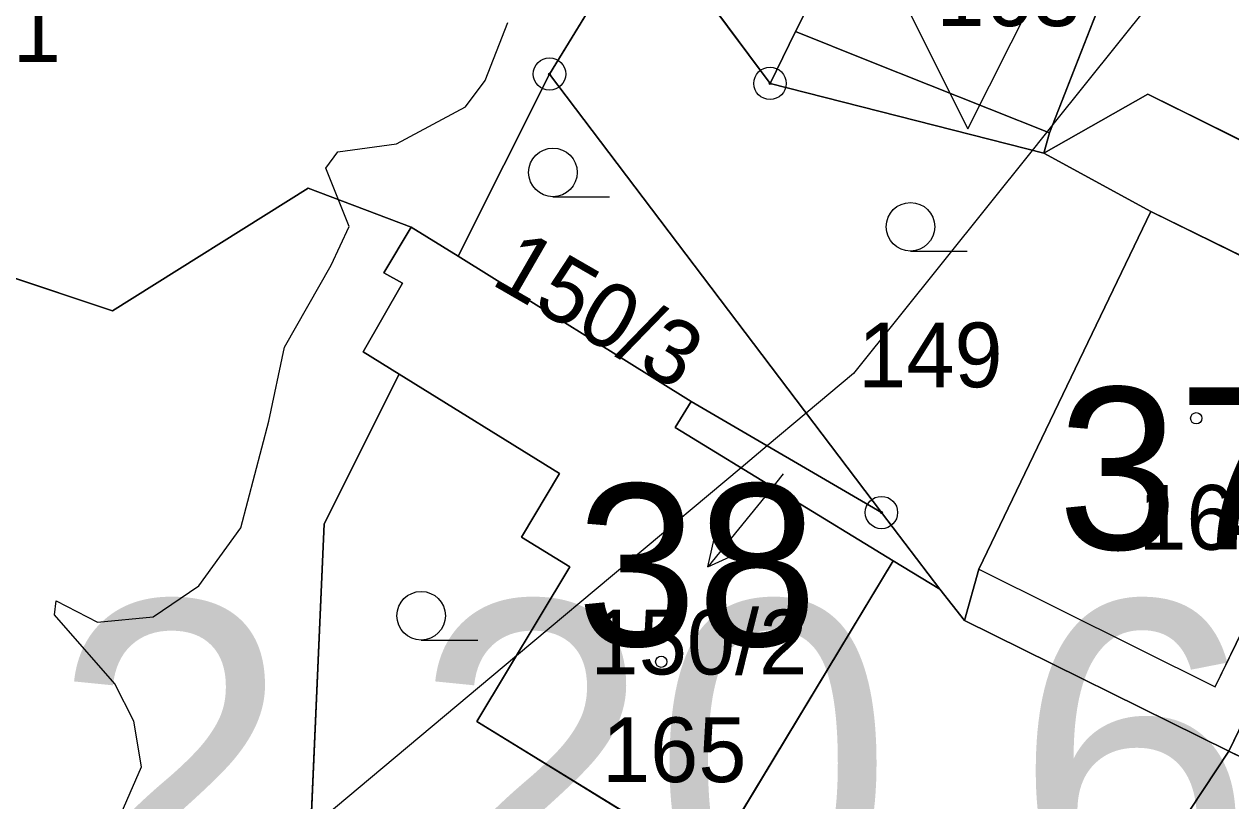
# Model space of a CAD drawing. Extents: x -706130 to -698555, y -971544 to -967260.
# Drawn here: x -704406.86 to -704369.6, y -970257.43 to -970233.43 of the extents above; entities that cross this region are included whole.
import ezdxf

# ---------------------------------------------------------------- set-up
doc = ezdxf.new("R2010")
doc.units = 0
for name, color, linetype in [('Architektonicky cenná stavba S', 7, 'Continuous'), ('BPEJ hranice S', 7, 'Continuous'), ('BPEJ I-II trida ochrany S', 7, 'Continuous'), ('Docházková izochrona - BUS S', 7, 'Continuous'), ('Docházková izochrona - VLAK N', 7, 'Continuous'), ('KN_Budovy', 7, 'Continuous'), ('KN_Budovy_cisla_domovni', 7, 'Continuous'), ('KN_Hranice_parcel', 7, 'Continuous'), ('KN_Hranice_parcel_vnitrni_kresba', 7, 'Continuous'), ('KN_Parcelni cisla', 7, 'Continuous'), ('KN_Parcelni cisla_sipky', 7, 'Continuous'), ('KN_Polygon parcely', 7, 'Continuous'), ('KN_POZEMKY_13_ZASTAVENA PLOCHA', 7, 'Continuous'), ('KN_POZEMKY_14_OSTATNI PLOCHA', 7, 'Continuous'), ('KN_POZEMKY_5_ZAHRADA', 7, 'Continuous'), ('KN_VYUZITI_17_ostatni plocha_ostatni komunikace', 7, 'Continuous'), ('KN_VYUZITI_23_ostatni plocha_manipulacni plocha', 7, 'Continuous'), ('KN_Značky bodu BP', 7, 'Continuous'), ('KN_Značky budov', 7, 'Continuous'), ('KN_Značky kultur', 7, 'Continuous'), ('Regulační kódy zastavěné S', 7, 'Continuous'), ('Záplavové území stanovene S', 7, 'Continuous')]:
    doc.layers.add(name, color=color, linetype=linetype)

msp = doc.modelspace()

# ---------------------------------------------------------------- linework, layer by layer
at = {"layer": 'Architektonicky cenná stavba S'}
msp.add_lwpolyline([(-704377.717, -970224.668), (-704379.717, -970228.668), (-704383.717, -970230.668), (-704379.717, -970232.668), (-704377.717, -970236.668), (-704375.717, -970232.668), (-704371.717, -970230.668), (-704375.717, -970228.668)], close=True, dxfattribs=at)
at = {"layer": 'BPEJ hranice S'}
msp.add_lwpolyline([(-704367.782, -970225.844), (-704370.102, -970230.283), (-704375.1, -970236.533), (-704375.737, -970237.329), (-704381.252, -970244.227), (-704382.712, -970245.45), (-704383.916, -970246.459), (-704384.724, -970247.136), (-704391.663, -970252.952), (-704398.01, -970258.272), (-704400.038, -970259.971), (-704404.172, -970263.437), (-704405.573, -970264.137), (-704409.891, -970266.297), (-704417.181, -970269.944), (-704427.092, -970270.254), (-704432.635, -970270.254), (-704437.933, -970270.254), (-704450.012, -970264.987)], dxfattribs=at)
at = {"layer": 'BPEJ I-II trida ochrany S'}
for p, q in [((-704375.38, -970237.42), (-704375.737, -970237.329)), ((-704372.07, -970239.22), (-704375.38, -970237.42)), ((-704377.38, -970250.27), (-704372.07, -970239.22)), ((-704382.712, -970245.45), (-704383.916, -970246.459)), ((-704383.916, -970246.459), (-704383.916, -970246.459)), ((-704384.724, -970247.136), (-704380.03, -970250.01)), ((-704380.03, -970250.01), (-704378.59, -970250.89)), ((-704377.82, -970251.86), (-704377.38, -970250.27)), ((-704378.59, -970250.89), (-704377.82, -970251.86)), ((-704392.88, -970254.98), (-704391.662, -970252.951)), ((-704385.69, -970259.4), (-704392.88, -970254.98))]:
    msp.add_line(p, q, dxfattribs=at)
for points in [[(-704375.737, -970237.329), (-704375.737, -970237.329), (-704381.252, -970244.227), (-704382.712, -970245.45), (-704382.712, -970245.45)], [(-704383.916, -970246.459), (-704384.724, -970247.136), (-704384.724, -970247.136)], [(-704391.662, -970252.951), (-704391.663, -970252.952), (-704398.01, -970258.272)]]:
    msp.add_lwpolyline(points, dxfattribs=at)
at = {"layer": 'Docházková izochrona - BUS S'}
msp.add_arc((-704361.829, -969946.93), 400, 155.51821, 17.33949, dxfattribs=at)
at = {"layer": 'Docházková izochrona - VLAK N'}
msp.add_circle((-704165.451, -969778.767), 800, dxfattribs=at)
at = {"layer": 'KN_Budovy'}
for points in [[(-704385.39, -970230.55), (-704382.18, -970231.93), (-704383.04, -970233.66), (-704380.79, -970234.56), (-704375.2, -970236.79), (-704371.02, -970226.09), (-704376.75, -970223.62), (-704378.47, -970227.61), (-704380.88, -970226.58), (-704380.37, -970225.41), (-704381.49, -970224.93), (-704382.03, -970226.17), (-704383.27, -970225.63)], [(-704372.07, -970239.22), (-704377.38, -970250.27), (-704370.08, -970253.91), (-704365.36, -970244.15), (-704368.12, -970242.72), (-704367.55, -970241.44)], [(-704395.18, -970241.43), (-704396.39, -970243.55), (-704395.28, -970244.24), (-704390.33, -970247.31), (-704391.5, -970249.28), (-704390.01, -970250.2), (-704392.88, -970254.98), (-704385.69, -970259.4), (-704380.03, -970250.01), (-704386.76, -970245.89), (-704386.26, -970245.09), (-704393.46, -970240.6), (-704394.91, -970239.7), (-704395.76, -970241.11)]]:
    msp.add_lwpolyline(points, close=True, dxfattribs=at)
at = {"layer": 'KN_Hranice_parcel'}
for p, q in [((-704388.54, -970231.53), (-704390.64, -970234.97)), ((-704404.13, -970242.29), (-704430.43, -970233.49)), ((-704393.46, -970240.6), (-704390.64, -970234.97)), ((-704390.64, -970234.97), (-704380.39, -970248.52)), ((-704383.83, -970235.26), (-704375.38, -970237.42)), ((-704372.07, -970239.22), (-704375.38, -970237.42)), ((-704393.46, -970240.6), (-704394.91, -970239.7)), ((-704386.26, -970245.09), (-704393.46, -970240.6)), ((-704396.39, -970243.55), (-704395.28, -970244.24)), ((-704395.28, -970244.24), (-704390.33, -970247.31)), ((-704380.39, -970248.52), (-704386.26, -970245.09)), ((-704390.33, -970247.31), (-704391.5, -970249.28)), ((-704380.39, -970248.52), (-704378.59, -970250.89)), ((-704385.69, -970259.4), (-704380.03, -970250.01)), ((-704378.59, -970250.89), (-704380.03, -970250.01)), ((-704378.59, -970250.89), (-704377.82, -970251.86)), ((-704377.82, -970251.86), (-704369.66, -970255.89)), ((-704374.96, -970263.92), (-704369.66, -970255.89))]:
    msp.add_line(p, q, dxfattribs=at)
for points in [[(-704371.02, -970226.09), (-704376.75, -970223.62), (-704378.47, -970227.61), (-704380.88, -970226.58), (-704380.37, -970225.41), (-704381.49, -970224.93), (-704382.03, -970226.17), (-704383.27, -970225.63), (-704385.39, -970230.55), (-704382.18, -970231.93), (-704383.04, -970233.66), (-704383.83, -970235.26)], [(-704375.38, -970237.42), (-704375.2, -970236.79), (-704371.02, -970226.09)], [(-704387.66, -970230.08), (-704385.82, -970232.57), (-704383.83, -970235.26)], [(-704375.38, -970237.42), (-704372.16, -970235.59), (-704358.88, -970242.2), (-704356.76, -970243.29)], [(-704394.91, -970239.7), (-704398.09, -970238.5), (-704404.13, -970242.29)], [(-704372.07, -970239.22), (-704377.38, -970250.27), (-704377.82, -970251.86)], [(-704369.66, -970255.89), (-704363.61, -970243.38), (-704367.55, -970241.44), (-704372.07, -970239.22)], [(-704394.91, -970239.7), (-704395.76, -970241.11), (-704395.18, -970241.43), (-704396.39, -970243.55)], [(-704398.11, -970260.57), (-704397.6, -970248.87), (-704395.28, -970244.24)], [(-704380.03, -970250.01), (-704386.76, -970245.89), (-704386.26, -970245.09)], [(-704391.5, -970249.28), (-704390.01, -970250.2), (-704392.88, -970254.98), (-704385.69, -970259.4)], [(-704369.66, -970255.89), (-704366.7, -970257.35), (-704364.41, -970258.54)]]:
    msp.add_lwpolyline(points, dxfattribs=at)
at = {"layer": 'KN_Hranice_parcel_vnitrni_kresba'}
for p, q in [((-704380.79, -970234.56), (-704383.04, -970233.66)), ((-704375.2, -970236.79), (-704380.79, -970234.56)), ((-704370.08, -970253.91), (-704365.36, -970244.15)), ((-704377.38, -970250.27), (-704370.08, -970253.91))]:
    msp.add_line(p, q, dxfattribs=at)
at = {"layer": 'KN_Parcelni cisla_sipky'}
for p, q in [((-704383.42, -970247.32), (-704383.86, -970247.87)), ((-704383.86, -970247.87), (-704385.749, -970250.202)), ((-704385.749, -970250.202), (-704385.507, -970249.109)), ((-704385.749, -970250.202), (-704384.729, -970249.739))]:
    msp.add_line(p, q, dxfattribs=at)
at = {"layer": 'KN_Polygon parcely'}
for points in [[(-704385.82, -970232.57), (-704383.83, -970235.26), (-704383.04, -970233.66), (-704382.18, -970231.93), (-704385.39, -970230.55), (-704383.27, -970225.63), (-704382.03, -970226.17), (-704381.49, -970224.93), (-704380.37, -970225.41), (-704380.88, -970226.58), (-704378.47, -970227.61), (-704376.75, -970223.62), (-704371.02, -970226.09), (-704370.83, -970216.86), (-704376.32, -970216.88), (-704376.3, -970214.28), (-704379.9, -970214.31), (-704387.66, -970230.08)], [(-704390.64, -970234.97), (-704388.54, -970231.53), (-704392.33, -970230.09), (-704424.7, -970218.11), (-704428.3, -970216.77), (-704429.79, -970221.55), (-704430.43, -970233.49), (-704404.13, -970242.29), (-704398.09, -970238.5), (-704394.91, -970239.7), (-704393.46, -970240.6)], [(-704366.78, -970217.54), (-704366.95, -970216.86), (-704370.83, -970216.86), (-704371.02, -970226.09), (-704375.2, -970236.79), (-704375.38, -970237.42), (-704372.16, -970235.59), (-704358.88, -970242.2), (-704356.76, -970243.29), (-704352.93, -970235.65), (-704355.53, -970234.99), (-704366.3, -970232.67), (-704367.39, -970230.26), (-704368.52, -970217.51)], [(-704375.2, -970236.79), (-704371.02, -970226.09), (-704376.75, -970223.62), (-704378.47, -970227.61), (-704380.88, -970226.58), (-704380.37, -970225.41), (-704381.49, -970224.93), (-704382.03, -970226.17), (-704383.27, -970225.63), (-704385.39, -970230.55), (-704382.18, -970231.93), (-704383.04, -970233.66), (-704383.83, -970235.26), (-704375.38, -970237.42)], [(-704380.39, -970248.52), (-704378.59, -970250.89), (-704377.82, -970251.86), (-704377.38, -970250.27), (-704372.07, -970239.22), (-704375.38, -970237.42), (-704383.83, -970235.26), (-704385.82, -970232.57), (-704387.66, -970230.08), (-704388.54, -970231.53), (-704390.64, -970234.97)], [(-704398.09, -970238.5), (-704404.13, -970242.29), (-704430.43, -970233.49), (-704430.7, -970238.66), (-704432.24, -970260.61), (-704400.41, -970268.71), (-704400.21, -970267.99), (-704398.11, -970260.57), (-704397.6, -970248.87), (-704395.28, -970244.24), (-704396.39, -970243.55), (-704395.18, -970241.43), (-704395.76, -970241.11), (-704394.91, -970239.7)], [(-704386.26, -970245.09), (-704380.39, -970248.52), (-704390.64, -970234.97), (-704393.46, -970240.6)], [(-704356.76, -970243.29), (-704358.88, -970242.2), (-704372.16, -970235.59), (-704375.38, -970237.42), (-704372.07, -970239.22), (-704367.55, -970241.44), (-704363.61, -970243.38), (-704369.66, -970255.89), (-704366.7, -970257.35), (-704364.41, -970258.54)], [(-704363.61, -970243.38), (-704367.55, -970241.44), (-704372.07, -970239.22), (-704377.38, -970250.27), (-704377.82, -970251.86), (-704369.66, -970255.89)], [(-704385.69, -970259.4), (-704380.03, -970250.01), (-704386.76, -970245.89), (-704386.26, -970245.09), (-704393.46, -970240.6), (-704394.91, -970239.7), (-704395.76, -970241.11), (-704395.18, -970241.43), (-704396.39, -970243.55), (-704395.28, -970244.24), (-704390.33, -970247.31), (-704391.5, -970249.28), (-704390.01, -970250.2), (-704392.88, -970254.98)], [(-704395.28, -970244.24), (-704397.6, -970248.87), (-704398.11, -970260.57), (-704390.97, -970263.35), (-704389.35, -970263.14), (-704385.63, -970262.67), (-704383.23, -970262.49), (-704380.33, -970262.9), (-704385.69, -970259.4), (-704392.88, -970254.98), (-704390.01, -970250.2), (-704391.5, -970249.28), (-704390.33, -970247.31)], [(-704386.26, -970245.09), (-704386.76, -970245.89), (-704380.03, -970250.01), (-704378.59, -970250.89), (-704380.39, -970248.52)], [(-704385.69, -970259.4), (-704380.33, -970262.9), (-704375.02, -970264.76), (-704374.96, -970263.92), (-704369.66, -970255.89), (-704377.82, -970251.86), (-704378.59, -970250.89), (-704380.03, -970250.01)], [(-704370.77, -970265.5), (-704369.07, -970266.34), (-704364.41, -970258.54), (-704366.7, -970257.35), (-704369.66, -970255.89), (-704374.96, -970263.92)]]:
    msp.add_lwpolyline(points, close=True, dxfattribs=at)
at = {"layer": 'KN_POZEMKY_13_ZASTAVENA PLOCHA'}
for p, q in [((-704371.02, -970226.09), (-704375.2, -970236.79)), ((-704383.04, -970233.66), (-704382.18, -970231.93)), ((-704383.83, -970235.26), (-704383.04, -970233.66)), ((-704375.38, -970237.42), (-704383.83, -970235.26)), ((-704375.2, -970236.79), (-704375.38, -970237.42)), ((-704377.38, -970250.27), (-704372.07, -970239.22)), ((-704372.07, -970239.22), (-704367.55, -970241.44)), ((-704395.76, -970241.11), (-704394.91, -970239.7)), ((-704394.91, -970239.7), (-704393.46, -970240.6)), ((-704393.46, -970240.6), (-704386.26, -970245.09)), ((-704395.18, -970241.43), (-704395.76, -970241.11)), ((-704396.39, -970243.55), (-704395.18, -970241.43)), ((-704363.61, -970243.38), (-704369.66, -970255.89)), ((-704395.28, -970244.24), (-704396.39, -970243.55)), ((-704390.33, -970247.31), (-704395.28, -970244.24)), ((-704386.26, -970245.09), (-704386.76, -970245.89)), ((-704386.76, -970245.89), (-704380.03, -970250.01)), ((-704391.5, -970249.28), (-704390.33, -970247.31)), ((-704390.01, -970250.2), (-704391.5, -970249.28)), ((-704392.88, -970254.98), (-704390.01, -970250.2)), ((-704380.03, -970250.01), (-704385.69, -970259.4)), ((-704377.82, -970251.86), (-704377.38, -970250.27)), ((-704369.66, -970255.89), (-704377.82, -970251.86)), ((-704385.69, -970259.4), (-704392.88, -970254.98))]:
    msp.add_line(p, q, dxfattribs=at)
at = {"layer": 'KN_POZEMKY_14_OSTATNI PLOCHA'}
for p, q in [((-704375.2, -970236.79), (-704371.02, -970226.09)), ((-704382.18, -970231.93), (-704383.04, -970233.66)), ((-704383.83, -970235.26), (-704385.82, -970232.57)), ((-704383.04, -970233.66), (-704383.83, -970235.26)), ((-704372.16, -970235.59), (-704375.38, -970237.42)), ((-704375.38, -970237.42), (-704372.16, -970235.59)), ((-704358.88, -970242.2), (-704372.16, -970235.59)), ((-704372.16, -970235.59), (-704358.88, -970242.2)), ((-704375.38, -970237.42), (-704375.2, -970236.79)), ((-704372.07, -970239.22), (-704375.38, -970237.42)), ((-704367.55, -970241.44), (-704372.07, -970239.22)), ((-704369.66, -970255.89), (-704363.61, -970243.38)), ((-704385.69, -970259.4), (-704380.03, -970250.01)), ((-704380.03, -970250.01), (-704378.59, -970250.89)), ((-704378.59, -970250.89), (-704377.82, -970251.86)), ((-704377.82, -970251.86), (-704369.66, -970255.89)), ((-704369.66, -970255.89), (-704374.96, -970263.92)), ((-704374.96, -970263.92), (-704369.66, -970255.89)), ((-704366.7, -970257.35), (-704369.66, -970255.89)), ((-704369.66, -970255.89), (-704366.7, -970257.35))]:
    msp.add_line(p, q, dxfattribs=at)
at = {"layer": 'KN_POZEMKY_5_ZAHRADA'}
for p, q in [((-704388.54, -970231.53), (-704390.64, -970234.97)), ((-704390.64, -970234.97), (-704388.54, -970231.53)), ((-704385.82, -970232.57), (-704383.83, -970235.26)), ((-704404.13, -970242.29), (-704430.43, -970233.49)), ((-704430.43, -970233.49), (-704404.13, -970242.29)), ((-704390.64, -970234.97), (-704393.46, -970240.6)), ((-704393.46, -970240.6), (-704390.64, -970234.97)), ((-704380.39, -970248.52), (-704390.64, -970234.97)), ((-704390.64, -970234.97), (-704380.39, -970248.52)), ((-704383.83, -970235.26), (-704375.38, -970237.42)), ((-704375.38, -970237.42), (-704372.07, -970239.22)), ((-704398.09, -970238.5), (-704404.13, -970242.29)), ((-704404.13, -970242.29), (-704398.09, -970238.5)), ((-704394.91, -970239.7), (-704398.09, -970238.5)), ((-704398.09, -970238.5), (-704394.91, -970239.7)), ((-704372.07, -970239.22), (-704377.38, -970250.27)), ((-704394.91, -970239.7), (-704395.76, -970241.11)), ((-704393.46, -970240.6), (-704394.91, -970239.7)), ((-704386.26, -970245.09), (-704393.46, -970240.6)), ((-704395.76, -970241.11), (-704395.18, -970241.43)), ((-704395.18, -970241.43), (-704396.39, -970243.55)), ((-704396.39, -970243.55), (-704395.28, -970244.24)), ((-704397.6, -970248.87), (-704395.28, -970244.24)), ((-704395.28, -970244.24), (-704397.6, -970248.87)), ((-704395.28, -970244.24), (-704390.33, -970247.31)), ((-704386.76, -970245.89), (-704386.26, -970245.09)), ((-704386.26, -970245.09), (-704380.39, -970248.52)), ((-704380.39, -970248.52), (-704386.26, -970245.09)), ((-704380.03, -970250.01), (-704386.76, -970245.89)), ((-704390.33, -970247.31), (-704391.5, -970249.28)), ((-704378.59, -970250.89), (-704380.39, -970248.52)), ((-704380.39, -970248.52), (-704378.59, -970250.89)), ((-704398.11, -970260.57), (-704397.6, -970248.87)), ((-704397.6, -970248.87), (-704398.11, -970260.57)), ((-704391.5, -970249.28), (-704390.01, -970250.2)), ((-704390.01, -970250.2), (-704392.88, -970254.98)), ((-704378.59, -970250.89), (-704380.03, -970250.01)), ((-704377.38, -970250.27), (-704377.82, -970251.86)), ((-704377.82, -970251.86), (-704378.59, -970250.89)), ((-704392.88, -970254.98), (-704385.69, -970259.4))]:
    msp.add_line(p, q, dxfattribs=at)
at = {"layer": 'KN_VYUZITI_17_ostatni plocha_ostatni komunikace'}
for p, q in [((-704385.69, -970259.4), (-704380.03, -970250.01)), ((-704380.03, -970250.01), (-704378.59, -970250.89)), ((-704378.59, -970250.89), (-704377.82, -970251.86)), ((-704377.82, -970251.86), (-704369.66, -970255.89)), ((-704369.66, -970255.89), (-704374.96, -970263.92)), ((-704374.96, -970263.92), (-704369.66, -970255.89)), ((-704369.66, -970255.89), (-704366.7, -970257.35))]:
    msp.add_line(p, q, dxfattribs=at)
at = {"layer": 'KN_VYUZITI_23_ostatni plocha_manipulacni plocha'}
for p, q in [((-704375.2, -970236.79), (-704371.02, -970226.09)), ((-704382.18, -970231.93), (-704383.04, -970233.66)), ((-704383.83, -970235.26), (-704385.82, -970232.57)), ((-704383.04, -970233.66), (-704383.83, -970235.26)), ((-704372.16, -970235.59), (-704375.38, -970237.42)), ((-704375.38, -970237.42), (-704372.16, -970235.59)), ((-704358.88, -970242.2), (-704372.16, -970235.59)), ((-704372.16, -970235.59), (-704358.88, -970242.2)), ((-704375.38, -970237.42), (-704375.2, -970236.79)), ((-704372.07, -970239.22), (-704375.38, -970237.42)), ((-704367.55, -970241.44), (-704372.07, -970239.22)), ((-704369.66, -970255.89), (-704363.61, -970243.38)), ((-704366.7, -970257.35), (-704369.66, -970255.89))]:
    msp.add_line(p, q, dxfattribs=at)
at = {"layer": 'KN_Značky bodu BP'}
for centre, radius in [((-704390.64, -970234.97), 0.5), ((-704390.64, -970234.97), 0.0303), ((-704383.83, -970235.26), 0.5), ((-704383.83, -970235.26), 0.0303), ((-704380.39, -970248.52), 0.5), ((-704380.39, -970248.52), 0.0303)]:
    msp.add_circle(centre, radius, dxfattribs=at)
at = {"layer": 'KN_Značky budov'}
for centre in [(-704370.667, -970245.609), (-704387.187, -970253.129)]:
    msp.add_circle(centre, 0.175, dxfattribs=at)
at = {"layer": 'KN_Značky kultur'}
for p, q in [((-704390.533, -970238.76), (-704388.783, -970238.76)), ((-704379.493, -970240.44), (-704377.743, -970240.44)), ((-704394.603, -970252.46), (-704392.853, -970252.46))]:
    msp.add_line(p, q, dxfattribs=at)
for centre in [(-704390.533, -970238.01), (-704379.493, -970239.69), (-704394.603, -970251.71)]:
    msp.add_circle(centre, 0.75, dxfattribs=at)
at = {"layer": 'Záplavové území stanovene S'}
msp.add_lwpolyline([(-704407.198, -970263.052), (-704404.667, -970259.667), (-704403.234, -970256.375), (-704403.47, -970254.97), (-704404.062, -970253.812), (-704405.928, -970251.678), (-704405.875, -970251.252), (-704404.594, -970251.906), (-704402.875, -970251.741), (-704401.466, -970250.784), (-704400.169, -970248.996), (-704399.304, -970245.696), (-704398.826, -970243.415), (-704397.378, -970240.878), (-704396.822, -970239.678), (-704397.548, -970237.875), (-704397.177, -970237.375), (-704395.363, -970237.125), (-704393.235, -970235.985), (-704392.625, -970235.167), (-704391.93, -970233.375)], dxfattribs=at)

# ---------------------------------------------------------------- texts
at = {"layer": 'KN_Budovy_cisla_domovni'}
for s, p in [('37', (-704374.947, -970249.654)), ('38', (-704389.806, -970252.639))]:
    msp.add_text(s, height=5, dxfattribs=at).set_placement(p)
at = {"layer": 'KN_Parcelni cisla'}
for s, p in [('163', (-704378.69, -970233.49)), ('1678/11', (-704415.39, -970234.6)), ('149', (-704381.11, -970244.65)), ('164', (-704372.46, -970249.669)), ('150/2', (-704389.373, -970253.523)), ('165', (-704389.02, -970256.85))]:
    msp.add_text(s, height=2, dxfattribs=at).set_placement(p)
msp.add_text('150/3', height=2, rotation=330, dxfattribs=at).set_placement((-704392.495, -970241.436))
at = {"layer": 'Regulační kódy zastavěné S'}
msp.add_text('SV.2.20.60', height=10, dxfattribs=at).set_placement((-704427.599, -970261.269))

doc.saveas('drawing.dxf')
